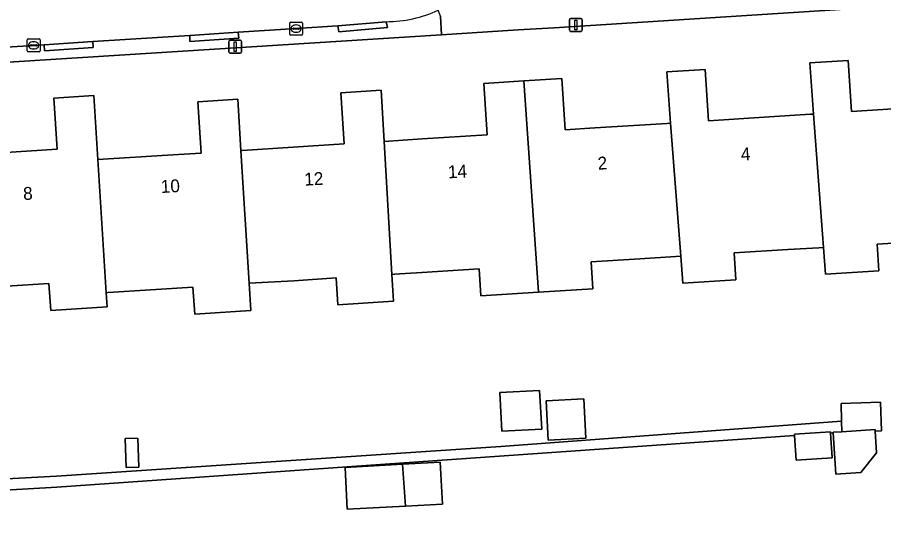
# Model space of a CAD drawing. Extents: x 159626 to 160723, y 388173 to 389416.
# Drawn here: x 160562.3 to 160629.6, y 388388.5 to 388427.7 of the extents above; entities that cross this region are included whole.
import ezdxf

# ---------------------------------------------------------------- set-up
doc = ezdxf.new("R2010")
doc.units = 0
for name, color, linetype in [('IMGEO_Erf', 7, 'Continuous'), ('IMGEO_Kolk', 7, 'Continuous'), ('IMGEO_Lichtmast', 7, 'Continuous'), ('IMGEO_Pand', 7, 'Continuous'), ('IMGEO_Pand_nummerreeks', 7, 'Continuous'), ('IMGEO_Rijbaan_lokaal_open', 7, 'Continuous'), ('IMGEO_Voetpad_open', 7, 'Continuous')]:
    doc.layers.add(name, color=color, linetype=linetype)

msp = doc.modelspace()

# ---------------------------------------------------------------- linework, layer by layer
at = {"layer": 'IMGEO_Erf'}
for points in [[(160707.968, 388433.592), (160604, 388426.895), (160601.214, 388426.719), (160595.247, 388426.341), (160524.215, 388421.845), (160522.486, 388421.748)], [(160560.99, 388417.155), (160565.362, 388417.432), (160565.11, 388421.422), (160568.21, 388421.619), (160568.523, 388416.631), (160574.347, 388417), (160576.55, 388417.14), (160576.298, 388421.13), (160579.402, 388421.326), (160579.645, 388417.341), (160579.744, 388417.347), (160587.664, 388417.848), (160587.413, 388421.834), (160590.542, 388422.033), (160590.776, 388418.042), (160593.733, 388418.235), (160598.792, 388418.565), (160598.532, 388422.555), (160601.635, 388422.75), (160604.61, 388422.937), (160604.865, 388418.945), (160607.165, 388419.092), (160612.798, 388419.451), (160613.056, 388419.467), (160612.752, 388423.455), (160615.735, 388423.646), (160615.99, 388419.654), (160620.326, 388419.931), (160623.923, 388420.16), (160624.178, 388420.176), (160623.882, 388424.165), (160626.86, 388424.355), (160627.115, 388420.363), (160631.59, 388420.649)], [(160635.716, 388410.471), (160629.129, 388410.06), (160629.259, 388407.964), (160625.105, 388407.704), (160624.949, 388409.798), (160624.586, 388409.775), (160622.161, 388409.624), (160617.998, 388409.364), (160618.129, 388407.268), (160614.004, 388407.01), (160613.845, 388409.103), (160613.456, 388409.079), (160610.662, 388408.905), (160606.868, 388408.668), (160606.998, 388406.572), (160602.794, 388406.309), (160598.31, 388406.029), (160598.174, 388408.133), (160593.722, 388407.847), (160591.587, 388407.71), (160591.382, 388407.697), (160591.505, 388405.6), (160587.18, 388405.322), (160587.045, 388407.417), (160583.751, 388407.205), (160580.277, 388407.005), (160580.406, 388404.886), (160576.051, 388404.606), (160575.916, 388406.701), (160572.622, 388406.49), (160569.329, 388406.278), (160569.174, 388406.268), (160569.243, 388405.17), (160564.858, 388404.888), (160564.723, 388406.983)], [(160564.723, 388406.983), (160561.429, 388406.771)], [(160536.69, 388390.471), (160565.317, 388391.995), (160599.857, 388394.307), (160626.356, 388396.282), (160626.313, 388397.643), (160629.372, 388397.738), (160629.441, 388395.506), (160628.957, 388395.491), (160629.065, 388393.796), (160627.847, 388392.274), (160625.904, 388392.149), (160625.699, 388395.363), (160625.501, 388395.349), (160625.624, 388393.429), (160622.807, 388393.248), (160622.685, 388395.152), (160565.345, 388391.14), (160536.755, 388389.483)]]:
    msp.add_lwpolyline(points, dxfattribs=at)
for points in [[(160599.766, 388398.493), (160602.872, 388398.662), (160603.035, 388395.657), (160599.929, 388395.488)], [(160603.38, 388397.845), (160606.305, 388398.004), (160606.47, 388394.955), (160603.546, 388394.797)], [(160571.644, 388394.96), (160571.718, 388392.691), (160570.728, 388392.659), (160570.653, 388394.927)], [(160592.219, 388392.916), (160595.136, 388393.075), (160595.313, 388389.814), (160592.444, 388389.659), (160587.917, 388389.413), (160587.74, 388392.673)]]:
    msp.add_lwpolyline(points, close=True, dxfattribs=at)
at = {"layer": 'IMGEO_Kolk'}
for p, q in [((160583.513, 388427.329), (160584.365, 388427.329)), ((160583.438, 388426.403), (160583.438, 388427.255)), ((160583.697, 388426.823), (160583.697, 388426.835)), ((160584.135, 388426.786), (160583.737, 388426.786)), ((160583.74, 388426.872), (160584.138, 388426.872)), ((160583.926, 388427.109), (160583.951, 388427.109)), ((160584.181, 388426.835), (160584.181, 388426.823)), ((160584.439, 388427.255), (160584.439, 388426.403)), ((160563.03, 388425.097), (160563.03, 388425.949)), ((160563.105, 388426.023), (160563.957, 388426.023)), ((160564.031, 388425.949), (160564.031, 388425.097)), ((160584.365, 388426.329), (160583.513, 388426.329)), ((160583.949, 388426.549), (160583.924, 388426.549)), ((160563.289, 388425.517), (160563.289, 388425.529)), ((160563.727, 388425.48), (160563.329, 388425.48)), ((160563.332, 388425.566), (160563.73, 388425.566)), ((160563.541, 388425.243), (160563.516, 388425.243)), ((160563.518, 388425.803), (160563.543, 388425.803)), ((160563.773, 388425.529), (160563.773, 388425.517)), ((160563.957, 388425.023), (160563.105, 388425.023))]:
    msp.add_line(p, q, dxfattribs=at)
for points in [[(160583.513, 388427.329), (160584.365, 388427.329)], [(160583.438, 388426.403), (160583.438, 388427.255)], [(160584.439, 388427.255), (160584.439, 388426.403)], [(160563.03, 388425.097), (160563.03, 388425.949)], [(160563.105, 388426.023), (160563.957, 388426.023)], [(160564.031, 388425.949), (160564.031, 388425.097)], [(160584.365, 388426.329), (160583.513, 388426.329)], [(160563.957, 388425.023), (160563.105, 388425.023)]]:
    msp.add_lwpolyline(points, dxfattribs=at)
for centre, radius, start, end in [((160583.515, 388427.253), 0.0765, 91.55205, 178.44795), ((160583.515, 388427.253), 0.0765, 91.55205, 178.44795), ((160584.363, 388427.253), 0.0765, 1.55205, 88.44795), ((160584.363, 388427.253), 0.0765, 1.55205, 88.44795), ((160583.737, 388426.832), 0.0403, 85.87752, 175.75265), ((160583.734, 388426.822), 0.0366, 178.93798, 274.71019), ((160584.138, 388426.829), 0.043, 264.86636, 352.45326), ((160584.142, 388426.834), 0.0386, 1.73085, 96.63898), ((160563.107, 388425.947), 0.0765, 91.55205, 178.44795), ((160563.107, 388425.947), 0.0765, 91.55205, 178.44795), ((160563.955, 388425.947), 0.0765, 1.55205, 88.44795), ((160563.955, 388425.947), 0.0765, 1.55205, 88.44795), ((160583.515, 388426.405), 0.0765, 181.55205, 268.44795), ((160583.515, 388426.405), 0.0765, 181.55205, 268.44795), ((160584.363, 388426.405), 0.0765, 271.55205, 358.44795), ((160584.363, 388426.405), 0.0765, 271.55205, 358.44795), ((160563.329, 388425.526), 0.0403, 85.87752, 175.75265), ((160563.326, 388425.516), 0.0366, 178.93798, 274.71019), ((160563.73, 388425.523), 0.043, 264.86636, 352.45326), ((160563.734, 388425.528), 0.0386, 1.73085, 96.63898), ((160563.107, 388425.099), 0.0765, 181.55205, 268.44795), ((160563.107, 388425.099), 0.0765, 181.55205, 268.44795), ((160563.955, 388425.099), 0.0765, 271.55205, 358.44795), ((160563.955, 388425.099), 0.0765, 271.55205, 358.44795)]:
    msp.add_arc(centre, radius, start, end, dxfattribs=at)
for centre, major_axis, ratio, start_param, end_param in [((160583.925, 388426.829), (-0.387, 0.002), 0.722429, 4.712389, 7.853982), ((160583.95, 388426.829), (-0.39, 0.002), 0.717154, 1.570796, 4.712389), ((160563.517, 388425.523), (-0.387, 0.002), 0.722429, 4.712389, 7.853982), ((160563.542, 388425.523), (-0.39, 0.002), 0.717154, 1.570796, 4.712389)]:
    msp.add_ellipse(centre, major_axis=major_axis, ratio=ratio, start_param=start_param, end_param=end_param, dxfattribs=at)
at = {"layer": 'IMGEO_Lichtmast'}
for p, q in [((160605.194, 388426.712), (160605.194, 388427.512)), ((160605.194, 388427.512), (160605.194, 388426.712)), ((160605.294, 388427.612), (160606.084, 388427.612)), ((160606.084, 388427.612), (160605.294, 388427.612)), ((160606.184, 388427.512), (160606.184, 388426.712)), ((160606.184, 388426.712), (160606.184, 388427.512)), ((160606.084, 388426.612), (160605.294, 388426.612)), ((160605.294, 388426.612), (160606.084, 388426.612)), ((160578.71, 388425.015), (160578.71, 388425.815)), ((160578.71, 388425.815), (160578.71, 388425.015)), ((160578.81, 388425.915), (160579.6, 388425.915)), ((160579.6, 388425.915), (160578.81, 388425.915)), ((160579.7, 388425.815), (160579.7, 388425.015)), ((160579.7, 388425.015), (160579.7, 388425.815)), ((160579.6, 388424.915), (160578.81, 388424.915)), ((160578.81, 388424.915), (160579.6, 388424.915))]:
    msp.add_line(p, q, dxfattribs=at)
for points in [[(160605.614, 388427.487), (160605.764, 388427.487), (160605.764, 388426.737), (160605.614, 388426.737), (160605.614, 388427.487)], [(160579.13, 388425.79), (160579.28, 388425.79), (160579.28, 388425.04), (160579.13, 388425.04), (160579.13, 388425.79)]]:
    msp.add_lwpolyline(points, dxfattribs=at)
for centre, start, end in [((160605.294, 388427.512), 90, 180), ((160605.294, 388427.512), 90, 180), ((160606.084, 388427.512), 0, 90), ((160606.084, 388427.512), 360, 90), ((160605.294, 388426.712), 180, 270), ((160605.294, 388426.712), 180, 270), ((160606.084, 388426.712), 270, 0), ((160606.084, 388426.712), 270, 0), ((160578.81, 388425.815), 90, 180), ((160578.81, 388425.815), 90, 180), ((160579.6, 388425.815), 0, 90), ((160579.6, 388425.815), 360, 90), ((160578.81, 388425.015), 180, 270), ((160578.81, 388425.015), 180, 270), ((160579.6, 388425.015), 270, 0), ((160579.6, 388425.015), 270, 0)]:
    msp.add_arc(centre, 0.1, start, end, dxfattribs=at)
at = {"layer": 'IMGEO_Pand'}
for points in [[(160635.277, 388420.884), (160635.038, 388420.869), (160631.59, 388420.649), (160627.115, 388420.363), (160626.86, 388424.355), (160623.882, 388424.165), (160624.178, 388420.176), (160624.949, 388409.798), (160625.105, 388407.704), (160629.259, 388407.964), (160629.129, 388410.06), (160635.716, 388410.471), (160636.058, 388410.492)], [(160624.178, 388420.176), (160623.923, 388420.16), (160620.326, 388419.931), (160615.99, 388419.654), (160615.735, 388423.646), (160612.752, 388423.455), (160613.056, 388419.467), (160613.845, 388409.103), (160614.004, 388407.01), (160618.129, 388407.268), (160617.998, 388409.364), (160622.161, 388409.624), (160624.586, 388409.775), (160624.949, 388409.798)], [(160601.635, 388422.75), (160598.532, 388422.555), (160598.792, 388418.565), (160593.733, 388418.235), (160590.776, 388418.042), (160591.382, 388407.697), (160591.587, 388407.71), (160593.722, 388407.847), (160598.174, 388408.133), (160598.31, 388406.029), (160602.794, 388406.309)], [(160613.056, 388419.467), (160612.798, 388419.451), (160607.165, 388419.092), (160604.865, 388418.945), (160604.61, 388422.937), (160601.635, 388422.75), (160602.794, 388406.309), (160606.998, 388406.572), (160606.868, 388408.668), (160610.662, 388408.905), (160613.456, 388409.079), (160613.845, 388409.103)], [(160590.776, 388418.042), (160590.542, 388422.033), (160587.413, 388421.834), (160587.664, 388417.848), (160579.744, 388417.347), (160579.645, 388417.341), (160580.277, 388407.005), (160583.751, 388407.205), (160587.045, 388407.417), (160587.18, 388405.322), (160591.505, 388405.6), (160591.382, 388407.697)], [(160568.523, 388416.631), (160568.21, 388421.619), (160565.11, 388421.422), (160565.362, 388417.432), (160560.99, 388417.155), (160557.336, 388416.924), (160557.979, 388406.55), (160558.136, 388406.56), (160561.429, 388406.771), (160564.723, 388406.983), (160564.858, 388404.888), (160569.243, 388405.17), (160569.174, 388406.268)], [(160579.645, 388417.341), (160579.402, 388421.326), (160576.298, 388421.13), (160576.55, 388417.14), (160574.347, 388417), (160568.523, 388416.631), (160569.174, 388406.268), (160569.329, 388406.278), (160572.622, 388406.49), (160575.916, 388406.701), (160576.051, 388404.606), (160580.406, 388404.886), (160580.277, 388407.005)], [(160599.766, 388398.493), (160599.929, 388395.488), (160603.035, 388395.657), (160602.872, 388398.662)], [(160603.38, 388397.845), (160603.546, 388394.797), (160606.47, 388394.955), (160606.305, 388398.004)], [(160629.372, 388397.738), (160626.313, 388397.643), (160626.356, 388396.282), (160626.382, 388395.451), (160628.949, 388395.616), (160628.957, 388395.491), (160629.441, 388395.506)], [(160628.957, 388395.491), (160628.949, 388395.616), (160626.382, 388395.451), (160625.696, 388395.407), (160625.699, 388395.363), (160625.904, 388392.149), (160627.847, 388392.274), (160629.065, 388393.796)], [(160571.718, 388392.691), (160571.644, 388394.96), (160570.653, 388394.927), (160570.728, 388392.659)], [(160625.501, 388395.349), (160625.496, 388395.431), (160622.679, 388395.251), (160622.685, 388395.152), (160622.807, 388393.248), (160625.624, 388393.429)], [(160592.219, 388392.916), (160587.74, 388392.673), (160587.917, 388389.413), (160592.444, 388389.659)], [(160592.219, 388392.916), (160592.444, 388389.659), (160595.313, 388389.814), (160595.136, 388393.075)]]:
    msp.add_lwpolyline(points, close=True, dxfattribs=at)
at = {"layer": 'IMGEO_Rijbaan_lokaal_open'}
msp.add_lwpolyline([(160589.246, 388432.16), (160582.875, 388431.76), (160580.341, 388431.601), (160576.515, 388431.361), (160570.704, 388430.997), (160566.68, 388430.744), (160560.282, 388430.343), (160552.399, 388429.848), (160525.71, 388428.174), (160525.02, 388428.13), (160525.26, 388423.086), (160542.187, 388424.165), (160545.973, 388424.406), (160553.441, 388424.882), (160557.225, 388425.123), (160564.339, 388425.575), (160568.126, 388425.816), (160575.667, 388426.296), (160579.442, 388426.54), (160583.939, 388426.83), (160587.17, 388427.056), (160590.95, 388427.367)], dxfattribs=at)
msp.add_arc((160590.971, 388436.758), 9.391, 269.87131, 295.31851, dxfattribs=at)
at = {"layer": 'IMGEO_Voetpad_open'}
for points in [[(160595.17, 388427.802), (160595.247, 388426.341), (160601.214, 388426.719), (160604, 388426.895), (160707.968, 388433.592)], [(160595.247, 388426.341), (160595.17, 388427.802), (160594.987, 388428.269)], [(160590.95, 388427.367), (160591.043, 388426.925), (160587.251, 388426.577), (160587.17, 388427.056), (160583.939, 388426.83), (160579.442, 388426.54), (160579.476, 388426.096), (160575.681, 388425.834), (160575.667, 388426.296), (160568.126, 388425.816), (160568.152, 388425.361), (160564.371, 388425.105), (160564.339, 388425.575), (160557.225, 388425.123), (160557.252, 388424.657), (160553.471, 388424.405), (160553.441, 388424.882), (160545.973, 388424.406), (160545.991, 388423.935), (160542.186, 388423.683), (160542.187, 388424.165), (160525.26, 388423.086), (160522.715, 388422.924), (160520.927, 388422.81)], [(160522.486, 388421.748), (160524.215, 388421.845), (160595.247, 388426.341)]]:
    msp.add_lwpolyline(points, dxfattribs=at)
for points in [[(160587.17, 388427.056), (160587.251, 388426.577), (160591.043, 388426.925), (160590.95, 388427.367)], [(160575.667, 388426.296), (160575.681, 388425.834), (160579.476, 388426.096), (160579.442, 388426.54)], [(160568.126, 388425.816), (160564.339, 388425.575), (160564.371, 388425.105), (160568.152, 388425.361)], [(160622.685, 388395.152), (160622.679, 388395.251), (160625.496, 388395.431), (160625.501, 388395.349), (160625.699, 388395.363), (160625.696, 388395.407), (160626.382, 388395.451), (160626.356, 388396.282), (160599.857, 388394.307), (160565.317, 388391.995), (160536.69, 388390.471), (160529.706, 388390.012), (160522.068, 388389.513), (160522.133, 388388.524), (160530.768, 388389.089), (160536.755, 388389.483), (160565.345, 388391.14)]]:
    msp.add_lwpolyline(points, close=True, dxfattribs=at)
msp.add_arc((160590.971, 388436.758), 9.391, 269.87131, 295.31851, dxfattribs=at)

# ---------------------------------------------------------------- texts
at = {"layer": 'IMGEO_Pand_nummerreeks'}
for s, rotation, p in [('4', 3.66693, (160618.548, 388416.549)), ('2', 3.66693, (160607.414, 388415.836)), ('14', 2.92781, (160595.767, 388415.17)), ('12', 2.92781, (160584.599, 388414.599)), ('8', 2.92781, (160562.737, 388413.481)), ('10', 2.92781, (160573.441, 388414.028))]:
    msp.add_text(s, height=1, rotation=rotation, dxfattribs=at).set_placement(p)

doc.saveas('drawing.dxf')
